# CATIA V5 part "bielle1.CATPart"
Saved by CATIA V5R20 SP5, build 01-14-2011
Part number: bielle1
Bounding box of the stored display mesh (mm): x -176.299 to -87.654, y -34.22 to -27.61, z 122.101 to 172.015
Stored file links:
  F:\iao\catia\projet iao\bielle1.CATPart
  F:\iao\catia\projet iao\fhartmann.CATProduct
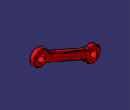
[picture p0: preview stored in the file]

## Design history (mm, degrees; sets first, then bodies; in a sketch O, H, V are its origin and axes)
External parameters (linked from other documents)
  External.bielle_longueur = 75 mm
  External.bielle1_epaisseur = 6.61 mm
  External.bielle_diametre_ext = 20 mm
  External.bielle_diametre_int = 10 mm
Set1
  Plane1: linked copy from another document
  Point1: linked copy from another document
  Point2: linked copy from another document
  Plane2: linked copy from another document
  Point3: linked copy from another document
Body1 (main body)
  Sketch1 on Plane1, origin (-82.0724, 193.2285, 32.9323), H (0, 1, 0), V (-0.4007, 0, 0.9162)
    line L1 (-220.8385, 119.6251) -> (-227.4485, 119.6251)
    line L2 (-227.4485, 119.6251) -> (-227.4485, 129.6251)
    line L3 (-227.4485, 129.6251) -> (-220.8385, 129.6251)
    line L4 (-220.8385, 129.6251) -> (-220.8385, 119.6251)
    point P2 (-227.4485, 119.6251)
    point P4 (-220.8385, 129.6251)
    reference projected point E1 (-227.4485, 119.6251) from Point1
    reference projected point E2 (-220.8385, 129.6251) from Point2
    length L3 = 6.61 {= External.bielle1_epaisseur}
    parallelism: L1 L3, L2 L4
    perpendicularity: L1 L2
    coincidence: P2 E1, P4 E2
  Pad1: profile Sketch1, direction (0.9162, 0, 0.4007), length 37.5 {= External.bielle_longueur  /2}, opposite side length 37.5 {= External.bielle_longueur /2}
  Sketch2 on Plane2, origin (-75, -30.915, 0), H (-1, 0, 0), V (0, 0, 1)
    circle A1 centre (22.6544, 162.1409) radius 10
    point P1 (22.6544, 162.1409)
    reference projected point E1 (22.6544, 162.1409) from Point3
    radius A1 = 10 {= External.bielle_diametre_ext /2}
    coincidence: P1 E1
  Pad2: profile Sketch2, direction (0, 1, 0), length 3.305 {= External.bielle1_epaisseur /2}, opposite side length 3.305 {= External.bielle1_epaisseur /2}
  Sketch3 on face of Pad2, origin (-145, -27.61, 0), H (-1, 0, 0), V (0, 0, 1)
    point P1 (-47.3456, 162.1409)
    reference projected point E1 (-47.3456, 162.1409) from Point3
    coincidence: E1 P1
  Hole1: placed by Sketch3, at (-97.6544, -27.61, 162.1409) direction (0, -1, 0), diameter 10 {= External.bielle_diametre_int}, depth 6.61 {= External.bielle1_epaisseur}
  Fillet1: radius 5, on edge [face of Pad2 from Sketch2.A1 | face of Pad1 from Sketch1.L1]; edge [face of Pad2 from Sketch2.A1 | face of Pad1 from Sketch1.L3]
  Mirror1: of Pad2, Hole1, Fillet1, about Plane1
  Chamfer1: length 1, angle 45, on edge [face of Mirror1 | face of Mirror1] (x2)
